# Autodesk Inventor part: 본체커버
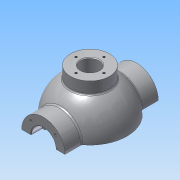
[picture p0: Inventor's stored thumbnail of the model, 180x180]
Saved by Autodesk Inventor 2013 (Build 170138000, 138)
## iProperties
Created: 2015-12
Part Number: 본체커버
Material: 알루미늄 6061
Document SubType Name: Modeling
Designer: mduedu
Density: 2.71 g/cm^3
Mass: 547.277 g
Surface Area: 428.16 cm^2
Volume: 201.947 cm^3
Author: mduedu
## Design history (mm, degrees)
sketch "스케치1"
  geometry: L1 (-53, 0)-(53, 0); A1 r 53 centre (0, 0) between (53, 0) and (-53, 0); 2 further points
  constraints: 2 coincident, 2 end point, 2 point on circle, 1 centre point, 1 horizontal, 1 midpoint
  dimensions: "d0" = 53 radius of A1
revolve "회전1" sketch "스케치1" stored, may be unused: angle "d2" = 90 deg
feature "쉘1" dims "d11" = 10
node "작업 평면1"
sketch "스케치2"
  geometry: C1 r 31 at (0, 0); 1 further point
  constraints: 1 centre point, 1 coincident
  dimensions: "d4" = 62 diameter of C1
extrude "돌출1" join sketch "스케치2" stored distance "d5" = 10; taper "d6" = 0 deg
hole "구멍1" diameter "d14" = 35; stored, may be unused: countersink angle "d18" = 90 deg, drill point angle "d20" = 0 deg; dims "d12" = 10, "d13" = 10, "d15" = 6, "d16" = 4, "d17" = 2, "d19" = 16
hole "구멍2" diameter "d23" = 27; stored, may be unused: countersink angle "d27" = 90 deg, drill point angle "d29" = 0 deg; dims "d21" = 10, "d22" = 10, "d24" = 6, "d25" = 4, "d26" = 2, "d28" = 16
fillet "모깎기1" dims "d30" = 0.3
chamfer "모따기1" distance "d40" = 1; stored, may be unused: second distance "d41" = 2, angle "d42" = 45 deg
sketch "스케치4"
  geometry: L1 (0, 0)-(0, -25); L2 (0, 0)-(-17.678, -17.678); A1 r 25 centre (0, 0) between (-17.678, -17.678) and (0, -25); 1 further point
  constraints: 4 end point, 2 point on circle, 1 centre point, 1 coincident, 1 vertical
  dimensions: "d43" = 50 diameter of A1; "d47" = 45 deg angle of L1 L2
hole "구멍4" sketch "스케치4" at (-17.678, -17.678) diameter "d49" = 3.242; stored, may be unused: countersink angle "d53" = 90 deg, drill point angle "d55" = 118 deg; dims "d50" = 11, "d51" = 4, "d52" = 2, "d54" = 13
node "작업 평면3"
sketch "스케치6"
  geometry: C1 r 65 at (0, 0); 1 further point
  constraints: 1 centre point, 1 coincident
  dimensions: "d78" = 130 diameter of C1
extrude "돌출3" join sketch "스케치6" distance "d80" = 10; taper "d81" = 0 deg
sketch "스케치7"
  geometry: C1 r 20 at (0, 0); 1 further point
  constraints: 1 centre point, 1 coincident
  dimensions: "d82" = 40 diameter of C1
extrude "돌출4" join sketch "스케치7" stored distance "d84" = 10; taper "d85" = 0 deg
sketch "스케치8"
  geometry: 2 further points
  constraints: 1 coincident
hole "구멍6" sketch "스케치8" at (0, 0) diameter "d86" = 20; stored, may be unused: countersink angle "d90" = 90 deg, drill point angle "d92" = 118 deg; dims "d87" = 7, "d88" = 40, "d89" = 5, "d91" = 10
fillet "모깎기2" dims "d93" = 0.3
sketch "스케치9"
  geometry: L1 (65, -75)-(-65, -75) reference; L2 (-45, -75)-(-38.245, -36.692); A1 r 53 centre (0, 0) between (42.988, 31) and (42.988, -31) reference; 1 further point
  constraints: 2 end point, 1 point on circle, 1 point on line
  dimensions: "d94" = 45 horizontal distance of L2.start point (0, 0); "d95" = 80 deg angle of L2 L1
feature "리브1" sketch "스케치9" dims "d96" = 1, "d97" = 8, "d98" = 0, "d99" = 0, "d100" = 1, "d101" = 1
sketch "스케치10"
  geometry: L1 (0, 0)-(0, -55); L2 (0, 0)-(-38.891, -38.891); A1 r 55 centre (0, 0) between (0, -55) and (-38.891, -38.891); 2 further points
  constraints: 4 end point, 2 coincident, 2 point on circle, 1 centre point, 1 vertical
  dimensions: "d105" = 110 diameter of A1; "d107" = 45 deg angle of L1 L2
hole "구멍7" sketch "스케치10" at (-38.891, -38.891) diameter "d109" = 10; stored, may be unused: countersink angle "d113" = 90 deg, drill point angle "d115" = 118 deg; dims "d110" = 7, "d111" = 40, "d112" = 5, "d114" = 10
fillet "모깎기3" dims "d120" = 3
fillet "모깎기4" dims "d121" = 3, "d122" = 3
fillet "모깎기5" dims "d123" = 3
fillet "모깎기6" dims "d124" = 3
sketch "스케치11"
  geometry: C1 r 5 at (-38.891, 38.891) reference; C2 r 5 at (38.891, 38.891) reference; C3 r 5 at (38.891, -38.891) reference; C4 r 5 at (-38.891, -38.891) reference; C5 r 20 at (0, 0) reference; C6 r 65 at (0, 0) reference; 1 further point
  constraints: 3 other
feature "엠보싱1" sketch "스케치11" dims "d125" = 0.5, "d126" = 0
sketch "스케치12"
  geometry: L1 (0, 100)-(0, -100); L2 (0, 100)-(-150, 100); L3 (-150, 100)-(-150, -100); L4 (-150, -100)-(0, -100); 2 further points
  constraints: 8 end point, 3 perpendicular, 1 coincident, 1 midpoint, 1 vertical
  dimensions: "d127" = 200 distance of L2.end L3.end; "d129" = 150 distance of L3.end L1.end
extrude "돌출5" cut sketch "스케치12" stored distance "d130" = 10; taper "d131" = 0 deg
node "작업 평면4"
sketch "스케치16"
  geometry: C1 r 28 at (0, 0); 1 further point
  constraints: 1 centre point, 1 coincident
  dimensions: "d148" = 56 diameter of C1
extrude "돌출9" join sketch "스케치16" stored distance "d150" = 5; taper "d151" = 0 deg
hole "구멍8" diameter "d154" = 26; stored, may be unused: countersink angle "d158" = 90 deg, drill point angle "d160" = 118 deg; dims "d152" = 10, "d153" = 10, "d155" = 6, "d156" = 4, "d157" = 2, "d159" = 8
sketch "스케치17" dims "d161" = 40
  geometry: 3 further points
  constraints: 2 vertical alignment, 1 coincident, 2 other
hole "구멍9" sketch "스케치17" at (0, 20) diameter "d163" = 3.242; stored, may be unused: countersink angle "d167" = 90 deg, drill point angle "d169" = 118 deg; dims "d164" = 8, "d165" = 4, "d166" = 2, "d168" = 10
fillet "모깎기11" dims "d173" = 3
chamfer "모따기2" distance "d174" = 1; stored, may be unused: second distance "d175" = 2, angle "d176" = 45 deg
node "솔리드1"
mirror "대칭1"
mirror "대칭2"
pattern_circular "원형 패턴1" dims angle "d57" = 360 deg
mirror "대칭3"
pattern_circular "원형 패턴3" dims angle "d103" = 360 deg
pattern_circular "원형 패턴4" dims "d40" = 1, angle "d118" = 360 deg
pattern_circular "원형 패턴5" dims angle "d171" = 360 deg
node "투영된 루프1"
other parameters: "d3" = 67, "d77" = -85, "d147" = 62
